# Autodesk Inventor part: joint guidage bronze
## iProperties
Created: 2011-09
Part Number: joint guidage bronze
Document SubType Name: Modeling
Designer: Dominique
Author: Dominique
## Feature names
1. Révolution1 [Revolution]
